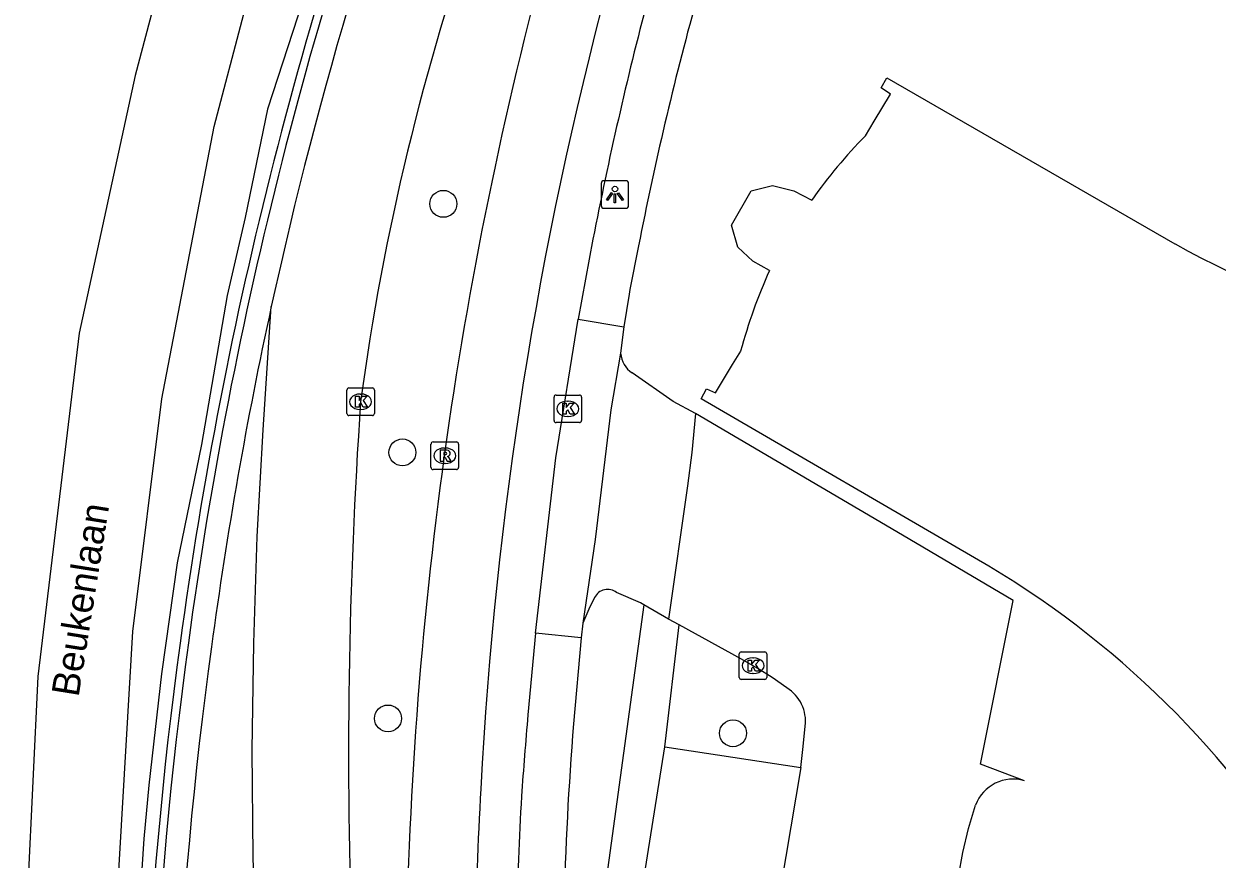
# Model space of a CAD drawing. Extents: x 159265 to 160143, y 383413 to 384319.
# Drawn here: x 159265.5 to 159308.85, y 384113.21 to 384143.55 of the extents above; entities that cross this region are included whole.
import ezdxf

# ---------------------------------------------------------------- set-up
doc = ezdxf.new("R2010")
doc.units = 0
for name, color, linetype in [('IMGEO_Boom', 7, 'Continuous'), ('IMGEO_Haag', 7, 'Continuous'), ('IMGEO_Kolk', 7, 'Continuous'), ('IMGEO_Lichtpunt', 7, 'Continuous'), ('IMGEO_Lijnafwatering', 7, 'Continuous'), ('IMGEO_Muur', 7, 'Continuous'), ('IMGEO_Openbare_ruimte_label', 7, 'Continuous'), ('IMGEO_Pand', 7, 'Continuous'), ('IMGEO_Parkeervlak_open', 7, 'Continuous'), ('IMGEO_Rijbaan_lokaal_gesloten', 7, 'Continuous'), ('IMGEO_Rijbaan_lokaal_open', 7, 'Continuous'), ('IMGEO_Rijbaan_regionaal_gesloten', 7, 'Continuous'), ('IMGEO_Rioolput', 7, 'Continuous'), ('IMGEO_Voetpad_open', 7, 'Continuous')]:
    doc.layers.add(name, color=color, linetype=linetype)

msp = doc.modelspace()

# ---------------------------------------------------------------- linework, layer by layer
at = {"layer": 'IMGEO_Boom'}
for centre in [(159280.737, 384137.016), (159279.251, 384127.986), (159278.726, 384118.322), (159291.259, 384117.786)]:
    msp.add_circle(centre, 0.489, dxfattribs=at)
at = {"layer": 'IMGEO_Haag'}
for points in [[(159288.025, 384122.449), (159285.24, 384102.132)], [(159288.782, 384117.294), (159289.307, 384121.722)]]:
    msp.add_lwpolyline(points, dxfattribs=at)
at = {"layer": 'IMGEO_Kolk'}
for p, q in [((159277.23, 384129.401), (159277.23, 384130.253)), ((159277.305, 384130.327), (159278.157, 384130.327)), ((159277.718, 384130.107), (159277.743, 384130.107)), ((159278.231, 384130.253), (159278.231, 384129.401)), ((159284.757, 384129.144), (159284.757, 384129.996)), ((159284.832, 384130.07), (159285.684, 384130.07)), ((159285.245, 384129.85), (159285.27, 384129.85)), ((159285.758, 384129.996), (159285.758, 384129.144)), ((159278.157, 384129.327), (159277.305, 384129.327)), ((159277.741, 384129.547), (159277.716, 384129.547)), ((159285.268, 384129.29), (159285.243, 384129.29)), ((159285.684, 384129.07), (159284.832, 384129.07)), ((159291.488, 384119.813), (159291.488, 384120.665)), ((159291.563, 384120.739), (159292.415, 384120.739)), ((159292.489, 384120.665), (159292.489, 384119.813)), ((159291.976, 384120.519), (159292.001, 384120.519)), ((159292.415, 384119.739), (159291.563, 384119.739)), ((159291.999, 384119.959), (159291.974, 384119.959))]:
    msp.add_line(p, q, dxfattribs=at)
for points in [[(159277.23, 384129.401), (159277.23, 384130.253)], [(159277.305, 384130.327), (159278.157, 384130.327)], [(159278.231, 384130.253), (159278.231, 384129.401)], [(159277.551, 384130.027), (159277.674, 384130.027), (159277.674, 384129.876), (159277.804, 384130.027), (159277.968, 384130.027), (159277.822, 384129.876), (159277.975, 384129.627), (159277.823, 384129.627), (159277.738, 384129.791), (159277.674, 384129.724), (159277.674, 384129.627), (159277.551, 384129.627), (159277.551, 384130.027)], [(159284.757, 384129.144), (159284.757, 384129.996)], [(159284.832, 384130.07), (159285.684, 384130.07)], [(159285.078, 384129.77), (159285.201, 384129.77), (159285.201, 384129.619), (159285.331, 384129.77), (159285.495, 384129.77), (159285.349, 384129.619), (159285.502, 384129.37), (159285.35, 384129.37), (159285.265, 384129.534), (159285.201, 384129.467), (159285.201, 384129.37), (159285.078, 384129.37), (159285.078, 384129.77)], [(159285.758, 384129.996), (159285.758, 384129.144)], [(159278.157, 384129.327), (159277.305, 384129.327)], [(159285.684, 384129.07), (159284.832, 384129.07)], [(159291.488, 384119.813), (159291.488, 384120.665)], [(159291.563, 384120.739), (159292.415, 384120.739)], [(159292.489, 384120.665), (159292.489, 384119.813)], [(159291.809, 384120.439), (159291.932, 384120.439), (159291.932, 384120.288), (159292.062, 384120.439), (159292.226, 384120.439), (159292.08, 384120.288), (159292.233, 384120.039), (159292.081, 384120.039), (159291.996, 384120.203), (159291.932, 384120.136), (159291.932, 384120.039), (159291.809, 384120.039), (159291.809, 384120.439)], [(159292.415, 384119.739), (159291.563, 384119.739)]]:
    msp.add_lwpolyline(points, dxfattribs=at)
for centre, start, end in [((159277.307, 384130.251), 91.552, 178.448), ((159277.307, 384130.251), 91.552, 178.448), ((159278.155, 384130.251), 1.552, 88.448), ((159278.155, 384130.251), 1.552, 88.448), ((159284.834, 384129.994), 91.552, 178.448), ((159284.834, 384129.994), 91.552, 178.448), ((159285.682, 384129.994), 1.552, 88.448), ((159285.682, 384129.994), 1.552, 88.448), ((159277.307, 384129.403), 181.552, 268.448), ((159277.307, 384129.403), 181.552, 268.448), ((159278.155, 384129.403), 271.552, 358.448), ((159278.155, 384129.403), 271.552, 358.448), ((159284.834, 384129.146), 181.552, 268.448), ((159284.834, 384129.146), 181.552, 268.448), ((159285.682, 384129.146), 271.552, 358.448), ((159285.682, 384129.146), 271.552, 358.448), ((159291.565, 384120.663), 91.552, 178.448), ((159291.565, 384120.663), 91.552, 178.448), ((159292.413, 384120.663), 1.552, 88.448), ((159292.413, 384120.663), 1.552, 88.448), ((159291.565, 384119.815), 181.552, 268.448), ((159291.565, 384119.815), 181.552, 268.448), ((159292.413, 384119.815), 271.552, 358.448), ((159292.413, 384119.815), 271.552, 358.448)]:
    msp.add_arc(centre, 0.0765, start, end, dxfattribs=at)
for centre, major_axis, ratio, start_param, end_param in [((159277.717, 384129.827), (-0.387, 0.002), 0.722429, 4.712389, 7.853982), ((159277.742, 384129.827), (-0.39, 0.002), 0.717154, 1.570796, 4.712389), ((159285.244, 384129.57), (-0.387, 0.002), 0.722429, 4.712389, 7.853982), ((159285.269, 384129.57), (-0.39, 0.002), 0.717154, 1.570796, 4.712389), ((159291.975, 384120.239), (-0.387, 0.002), 0.722429, 4.712389, 7.853982), ((159292, 384120.239), (-0.39, 0.002), 0.717154, 1.570796, 4.712389)]:
    msp.add_ellipse(centre, major_axis=major_axis, ratio=ratio, start_param=start_param, end_param=end_param, dxfattribs=at)
at = {"layer": 'IMGEO_Lichtpunt'}
for p, q in [((159286.472, 384137.759), (159286.472, 384136.952)), ((159286.472, 384137.759), (159286.472, 384136.952)), ((159287.374, 384137.854), (159286.566, 384137.854)), ((159287.374, 384137.854), (159286.566, 384137.854)), ((159287.468, 384136.952), (159287.468, 384137.759)), ((159287.468, 384136.952), (159287.468, 384137.759)), ((159286.566, 384136.858), (159287.374, 384136.858)), ((159286.566, 384136.858), (159287.374, 384136.858))]:
    msp.add_line(p, q, dxfattribs=at)
for points in [[(159286.846, 384137.423), (159286.885, 384137.395), (159286.697, 384137.133), (159286.659, 384137.16), (159286.846, 384137.423)], [(159286.948, 384137.375), (159286.995, 384137.375), (159286.995, 384137.053), (159286.948, 384137.053), (159286.948, 384137.375)], [(159287.058, 384137.395), (159287.096, 384137.422), (159287.283, 384137.16), (159287.244, 384137.132), (159287.058, 384137.395)]]:
    msp.add_lwpolyline(points, dxfattribs=at)
msp.add_circle((159286.971, 384137.557), 0.0994, dxfattribs=at)
for centre, start, end in [((159286.566, 384137.759), 90, 180), ((159286.566, 384137.759), 90, 180), ((159287.374, 384137.759), 0, 90), ((159287.374, 384137.759), 0, 90), ((159286.566, 384136.952), 180, 270), ((159286.566, 384136.952), 180, 270), ((159287.374, 384136.952), 270, 0), ((159287.374, 384136.952), 270, 360)]:
    msp.add_arc(centre, 0.0946, start, end, dxfattribs=at)
at = {"layer": 'IMGEO_Lijnafwatering'}
for points in [[(159278.209, 384152.968), (159276.838, 384148.279), (159275.635, 384144.389), (159274.351, 384140.458), (159273.534, 384136.523), (159272.884, 384133.689)], [(159272.884, 384133.689), (159271.954, 384128.274), (159271.068, 384123.971), (159270.5, 384119.94), (159270.036, 384115.895), (159269.852, 384113.952)], [(159269.852, 384113.952), (159269.373, 384106.615), (159269.243, 384101.382), (159269.304, 384095.567), (159269.359, 384093.958)]]:
    msp.add_lwpolyline(points, dxfattribs=at)
at = {"layer": 'IMGEO_Muur'}
for centre, radius, start, end in [((159425.182, 384100.216), 155.412, 159.12324, 172.29276), ((159425.552, 384100.215), 155.483, 159.12785, 172.29126), ((159423.037, 384100.218), 153.287, 172.18571, 182.78791), ((159423.337, 384100.23), 153.287, 172.18571, 182.78791)]:
    msp.add_arc(centre, radius, start, end, dxfattribs=at)
at = {"layer": 'IMGEO_Pand'}
for points in [[(159296.074, 384139.492), (159296.393, 384140.022), (159296.982, 384141.002), (159296.641, 384141.23), (159296.849, 384141.591), (159307.319, 384135.563)], [(159292.584, 384134.59), (159291.987, 384134.938), (159291.441, 384135.445), (159291.207, 384136.242), (159291.923, 384137.483), (159292.7, 384137.679), (159293.473, 384137.484), (159294.124, 384137.155)], [(159300.56, 384123.849), (159290.103, 384129.936), (159290.293, 384130.291), (159290.62, 384130.145), (159291.247, 384131.185), (159291.539, 384131.67)]]:
    msp.add_lwpolyline(points, dxfattribs=at)
for centre, radius, start, end in [((159308.922, 384126.79), 18.067, 135.3262, 144.9903), ((159323.807, 384165.204), 33.918, 240.9151, 299.1543), ((159310.92, 384126.381), 20.09, 155.882, 164.7357), ((159283.186, 384094.74), 33.9, 0.9173, 59.1682)]:
    msp.add_arc(centre, radius, start, end, dxfattribs=at)
at = {"layer": 'IMGEO_Parkeervlak_open'}
for points in [[(159289.065, 384051.59), (159288.41, 384063.895), (159287.889, 384076.678), (159287.859, 384077.406), (159287.738, 384080.579), (159286.807, 384104.884), (159288.782, 384117.294)], [(159288.782, 384117.294), (159293.73, 384116.543)]]:
    msp.add_lwpolyline(points, dxfattribs=at)
at = {"layer": 'IMGEO_Rijbaan_lokaal_gesloten'}
for points in [[(159286.171, 384135.728), (159285.635, 384132.822)], [(159284.082, 384121.417), (159284.828, 384127.795), (159285.635, 384132.822)], [(159284.082, 384121.417), (159283.811, 384118.459)]]:
    msp.add_lwpolyline(points, dxfattribs=at)
for centre, radius, start, end in [((159423.048, 384108.462), 141.139, 164.98893, 177.03242), ((159425.213, 384108.568), 141.67, 165.33887, 168.94726), ((159430.159, 384105.361), 146.932, 174.88575, 176.04481), ((159404.598, 384108.67), 122.706, 176.68357, 182.04956), ((159413.502, 384108.141), 130.134, 176.75993, 180.77882)]:
    msp.add_arc(centre, radius, start, end, dxfattribs=at)
at = {"layer": 'IMGEO_Rijbaan_lokaal_open'}
for points in [[(159287.177, 384131.589), (159286.824, 384129.53), (159286.248, 384124.819), (159285.801, 384121.785)], [(159289.902, 384129.396), (159289.081, 384129.841), (159287.598, 384130.875)], [(159289.902, 384129.396), (159289.759, 384127.986), (159289.607, 384126.773), (159288.923, 384121.935)], [(159301.854, 384116.056), (159300.252, 384116.657), (159301.445, 384122.61), (159297.421, 384124.976), (159289.902, 384129.396)], [(159288.025, 384122.449), (159287.898, 384122.522), (159287.033, 384122.903)], [(159286.23, 384122.719), (159286.025, 384122.288), (159285.801, 384121.785)], [(159288.923, 384121.935), (159288.025, 384122.449)], [(159289.307, 384121.722), (159288.923, 384121.935)], [(159293.218, 384119.436), (159292.686, 384119.809), (159292.135, 384120.155), (159291.567, 384120.472), (159289.307, 384121.722)], [(159293.73, 384116.543), (159293.805, 384117.3), (159293.884, 384118.045)], [(159293.73, 384116.543), (159291.718, 384104.61), (159294.164, 384051.826)], [(159299.451, 384112.582), (159299.609, 384113.458), (159299.817, 384114.324), (159300.074, 384115.176)]]:
    msp.add_lwpolyline(points, dxfattribs=at)
for centre, radius, start, end in [((159427.827, 384107.491), 148.461, 165.47307, 180.11689), ((159288.117, 384131.662), 0.943, 184.4534, 236.5969), ((159286.709, 384122.473), 0.538, 52.976, 152.836), ((159292.464, 384118.22), 1.431, 352.9816, 58.1879), ((159301.436, 384114.662), 1.456, 73.3063, 159.3076)]:
    msp.add_arc(centre, radius, start, end, dxfattribs=at)
at = {"layer": 'IMGEO_Rijbaan_regionaal_gesloten'}
for points in [[(159272.525, 384029.091), (159272.497, 384029.26), (159271.874, 384037.989), (159270.771, 384065.944), (159268.949, 384097.91), (159268.741, 384109.268), (159269.455, 384121.477), (159270.512, 384129.935), (159272.41, 384139.83), (159275.639, 384152.115), (159279.125, 384161.573), (159284.708, 384174.33), (159290.18, 384185.037), (159296.673, 384195.241), (159303.494, 384203.99), (159314.075, 384215.561), (159324.375, 384224.349), (159337.861, 384233.763), (159344.188, 384237.881), (159349.775, 384241.197), (159359.142, 384246.764)], [(159280.211, 384172.631), (159274.487, 384158.497), (159272.013, 384150.923), (159269.535, 384141.678), (159267.507, 384132.324), (159266.005, 384119.851), (159265.496, 384109.233), (159267.965, 384029.162), (159271.62, 383998.252), (159277.018, 383952.804), (159311.634, 383770.65), (159326.117, 383701.416), (159334.862, 383664.196)], [(159280.23, 384022.862), (159279.558, 384025.055), (159278.733, 384028.916), (159277.705, 384034.522), (159276.941, 384040.17), (159276.444, 384045.847), (159276.303, 384048.072), (159275.571, 384067.538), (159274.696, 384088.98), (159274.434, 384096.225), (159273.932, 384109.416), (159273.823, 384113.295), (159273.795, 384117.175), (159273.846, 384121.055), (159273.978, 384124.933), (159274.189, 384128.808), (159274.487, 384133.288)]]:
    msp.add_lwpolyline(points, dxfattribs=at)
for centre, radius, start, end in [((159424.611, 384100.56), 153.65, 158.72636, 167.70168), ((159367.285, 384117.728), 90.369, 160.56066, 172.30615), ((159424.537, 384100.55), 153.58, 167.69205, 172.37815), ((159465.515, 384117.009), 188.222, 176.09503, 182.19401), ((159419.61, 384100.454), 148.711, 172.08963, 182.97221)]:
    msp.add_arc(centre, radius, start, end, dxfattribs=at)
at = {"layer": 'IMGEO_Rioolput'}
for p, q in [((159280.363, 384128.366), (159281.215, 384128.366)), ((159280.288, 384127.44), (159280.288, 384128.292)), ((159280.776, 384128.146), (159280.801, 384128.146)), ((159281.289, 384128.292), (159281.289, 384127.44)), ((159280.799, 384127.586), (159280.774, 384127.586)), ((159281.215, 384127.366), (159280.363, 384127.366))]:
    msp.add_line(p, q, dxfattribs=at)
for points in [[(159280.363, 384128.366), (159281.215, 384128.366)], [(159280.288, 384127.44), (159280.288, 384128.292)], [(159280.877, 384128.064), (159280.625, 384128.066), (159280.625, 384127.666)], [(159280.803, 384127.985), (159280.749, 384127.985), (159280.749, 384127.904)], [(159281.289, 384128.292), (159281.289, 384127.44)], [(159280.625, 384127.666), (159280.749, 384127.666), (159280.749, 384127.828), (159280.76, 384127.828)], [(159280.749, 384127.904), (159280.801, 384127.904)], [(159280.807, 384127.799), (159280.878, 384127.666), (159281.018, 384127.666), (159280.953, 384127.792)], [(159281.215, 384127.366), (159280.363, 384127.366)]]:
    msp.add_lwpolyline(points, dxfattribs=at)
for centre, radius, start, end in [((159280.365, 384128.29), 0.0765, 91.552, 178.448), ((159280.365, 384128.29), 0.0765, 91.552, 178.448), ((159281.213, 384128.29), 0.0765, 1.552, 88.448), ((159281.213, 384128.29), 0.0765, 1.552, 88.448), ((159280.809, 384127.889), 0.0964, 77.0061, 93.1865), ((159280.823, 384127.946), 0.0378, 276.6634, 79.6772), ((159280.876, 384127.954), 0.109, 350.3612, 89.416), ((159280.874, 384127.954), 0.112, 277.5842, 350.9817), ((159280.759, 384127.775), 0.0533, 26.0293, 88.6989), ((159280.785, 384128.093), 0.19, 274.7715, 282.9687), ((159280.858, 384127.739), 0.108, 29.5134, 73.7905), ((159280.365, 384127.442), 0.0765, 181.552, 268.448), ((159280.365, 384127.442), 0.0765, 181.552, 268.448), ((159281.213, 384127.442), 0.0765, 271.552, 358.448), ((159281.213, 384127.442), 0.0765, 271.552, 358.448)]:
    msp.add_arc(centre, radius, start, end, dxfattribs=at)
for centre, major_axis, ratio, start_param, end_param in [((159280.775, 384127.866), (-0.387, 0.002), 0.722429, 4.712389, 7.853982), ((159280.8, 384127.866), (-0.39, 0.002), 0.717154, 1.570796, 4.712389)]:
    msp.add_ellipse(centre, major_axis=major_axis, ratio=ratio, start_param=start_param, end_param=end_param, dxfattribs=at)
at = {"layer": 'IMGEO_Voetpad_open'}
for points in [[(159287.831, 384135.494), (159287.518, 384133.901), (159287.486, 384133.735), (159287.3, 384132.554)], [(159285.635, 384132.822), (159287.3, 384132.554)], [(159287.3, 384132.554), (159287.177, 384131.589)], [(159285.801, 384121.785), (159285.742, 384121.246)], [(159285.742, 384121.246), (159284.082, 384121.417)], [(159285.742, 384121.246), (159285.466, 384118.13)]]:
    msp.add_lwpolyline(points, dxfattribs=at)
for centre, radius, start, end in [((159406.164, 384112.394), 120.567, 164.62912, 168.95403), ((159413.7, 384107.977), 128.636, 175.47323, 181.52012)]:
    msp.add_arc(centre, radius, start, end, dxfattribs=at)

# ---------------------------------------------------------------- texts
at = {"layer": 'IMGEO_Openbare_ruimte_label'}
msp.add_text('Beukenlaan', height=1, rotation=80.9052, dxfattribs=at).set_placement((159267.482, 384119.075))

doc.saveas('drawing.dxf')
